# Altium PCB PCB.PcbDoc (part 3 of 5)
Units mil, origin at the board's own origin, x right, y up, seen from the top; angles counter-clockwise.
Board outline 8070.87 x 4448.94 mil, 4 copper layers (Top Layer, Layer 1, Layer 2, Bottom Layer), stack 23.756 mil thick; 263 components, 330 nets, 1677 pads, 1186 vias.
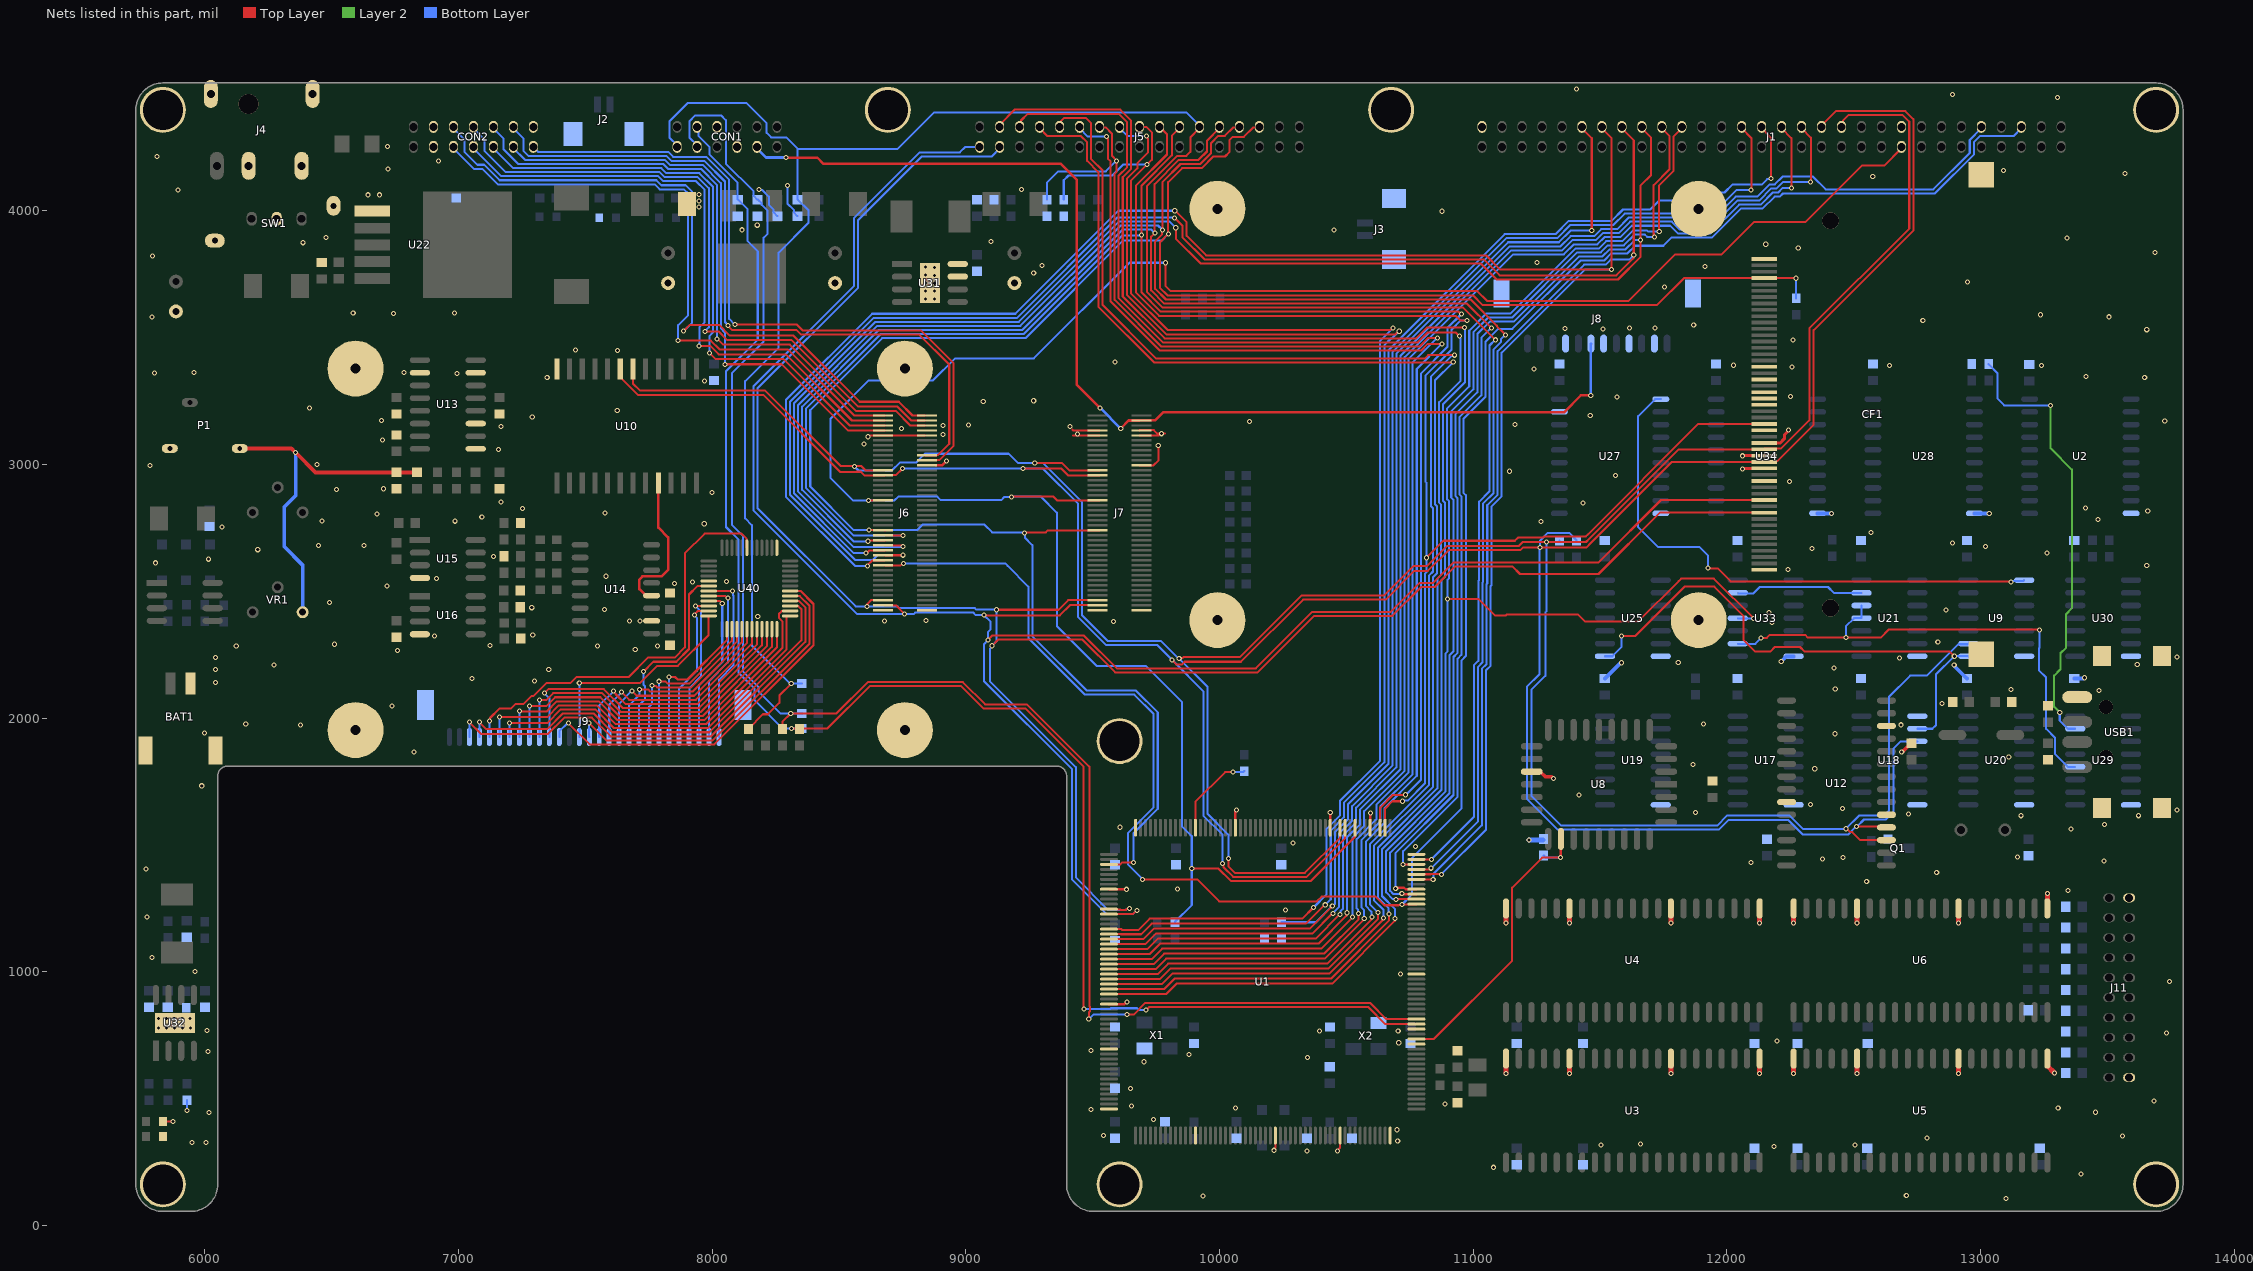
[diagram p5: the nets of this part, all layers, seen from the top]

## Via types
v1: diameter 20, hole 12, Top Layer to Bottom Layer, tented both sides, 1165 vias
v2: diameter 19.68, hole 11.81, Top Layer to Bottom Layer, tented both sides, 10 vias
v3: diameter 27.56, hole 27.56, Top Layer to Bottom Layer, 4 vias
v4: diameter 35.43, hole 35.43, Top Layer to Bottom Layer, 2 vias
v5: diameter 55.12, hole 55.12, Top Layer to Bottom Layer, 2 vias
v6: diameter 66.93, hole 66.93, Top Layer to Bottom Layer, 2 vias
v7: diameter 78.74, hole 78.74, Top Layer to Bottom Layer, 1 vias

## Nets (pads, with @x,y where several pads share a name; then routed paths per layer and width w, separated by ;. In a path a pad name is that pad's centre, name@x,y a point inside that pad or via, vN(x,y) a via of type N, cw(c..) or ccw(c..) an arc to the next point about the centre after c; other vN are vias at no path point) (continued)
D14: CF1.30 J5.3 J6.6 J7.6 U1.12 | length 8550.7
  Top Layer w8: v1(8611,2440) 8613.3,2442.3 8613.3,2451.3 8626.57,2464.57 J6.6@8681.1,2464.57 ; v1(9103.69,2285) 9103.77,2285 9128.33,2309.56 9459.19,2309.56 9588.75,2180 10150.49,2180 10373.49,2403 10681.76,2403 10794.76,2516 10848.01,2516 10930.01,2598 11155,2598 11185,2568 11494.61,2568 11736.25,2809.65 CF1.30@12147.64,2809.65 ; v1(9121.89,2427) 9366,2427 9403.57,2464.57 J7.6@9527.56,2464.57 ; U1.12@9564.65,1246.38 9565.37,1245.65 9609.24,1245.65 9611.89,1243 9630.11,1243 9634.82,1247.7 9642.7,1247.7 v1(9645,1250)
  Bottom Layer w8: v1@8609,2442 v1(8611,2440) ; v1(9103.69,2285) 9103.69,2281.75 9095,2273.07 9095,2145.49 9434,1806.49 9434,1371.63 9562.63,1243 9630.11,1243 9634.82,1247.7 9642.7,1247.7 v1(9645,1250) ; v1@9107,2285.56 9107,2288.93 9121.89,2303.82 v1(9121.89,2427) ; v1@9121.94,2427.06 9121,2428 9040.81,2428 9035.81,2433 8738,2433 8731,2440 v1(8611,2440) ; J5.3@9133.86,4251.97 9133.86,4246.06 9101.8,4214 8826.18,4214 8575.71,3963.54 8575.71,3697.09 8179,3300.37 8179,2826.63 8565.63,2440 v1(8611,2440)
D15: CF1.31 J5.1 J6.4 J7.4 U1.13 | length 8613.1
  Top Layer w8: J6.4@8681.1,2444.88 8682.02,2443.96 8725.11,2443.96 v1(8759,2410.07) ; v1(9072,2406) 9073,2405 9371,2405 9410.88,2444.88 J7.4@9527.56,2444.88 ; v1(9087.4,2307.78) 9105.19,2325.56 9465.82,2325.56 9595.37,2196 10143.86,2196 10366.86,2419 10675.14,2419 10788.14,2532 10841.38,2532 10923.38,2614 11495.35,2614 11741,2859.65 CF1.31@12147.64,2859.65 ; U1.13@9564.65,1226.69 9658.19,1226.69 9672.5,1241 v1(9675,1241)
  Bottom Layer w8: v1(8759,2410.07) 8572.93,2410.07 8163,2820 8163,3307 8559,3703 8559,3970.46 8818.54,4230 8977.04,4230 8999.01,4251.97 J5.1@9055.12,4251.97 ; v1@8761.71,2410.87 8762.51,2410.07 8794.87,2410.07 8800.8,2416 9030.18,2416 9040.18,2406 v1(9072,2406) 9098,2380 9098,2350.12 9088,2340.12 v1@9088,2307.78 ; v1(9087.4,2307.78) 9087.4,2306.4 9072,2291 9072,2145.86 9418,1799.86 9418,1365 9556,1227 9657.89,1227 9671.89,1241 v1(9675,1241)
DACK0#: J5.18 R11.2 U1.16 | length 5511.5
  Top Layer w8: U1.16@9564.65,1167.64 9613.99,1167.64 9617.89,1163.74 9679.74,1163.74 9725,1209 10327,1209 v1(10371,1253) ; J5.18@9685.04,4330.71 9712.29,4330.71 9734.06,4308.94 9734.06,4200.71 9716.36,4183 v1@9715,4183 ; v1(9714,4183) 9714,4182 9651,4119 9651,3675.27 9797.27,3529 10673.02,3529 10681.02,3537 v1(10683.7,3537)
  Bottom Layer w8: R11.2@9386.33,4044 9386.33,4120.33 9405,4139 9578,4139 9622,4183 v1(9714,4183) ; v1(10371,1253) 10423,1305 10423,1563.02 10475,1615.02 10475,1673 10634,1832 10634,3487.3 v1(10683.7,3537)
DACK1#: J1.30 R12.2 U1.18 | length 5453.9
  Top Layer w8: U1.18@9564.65,1128.27 9699.95,1128.27 9741.31,1169.63 10356.25,1169.63 10445,1258.38 v1(10445,1259.28) ; J1.30@12137.8,4330.71 12137.8,4324.8 12174,4288.6 12174,4128 v1(12175,4127)
  Bottom Layer w8: R12.2@10245,1195 10380.71,1195 v1(10445,1259.28) 10448.24,1259.28 10455,1266.04 10455,1549.76 10507,1601.76 10507,1659.75 10666,1818.75 10666,3449 11124.85,3907.85 11324.95,3907.85 11376.95,3959.85 11546.22,3959.85 11591.22,4004.85 11697.96,4004.85 11732.96,4039.85 11842.49,4039.85 11874.65,4072 11991.39,4072 12022.39,4103 12138.14,4103 12159.84,4124.7 12172.7,4124.7 v1(12175,4127)
DACK2#: J1.12 U1.20 | length 4665.6
  Top Layer w8: U1.20@9564.65,1088.9 9716.25,1088.9 9757.62,1130.26 10379.26,1130.26 v1(10475,1226) ; J1.12@11429.13,4330.71 11429.13,4324.8 11468,4285.94 v1(11468,3921.85)
  Bottom Layer w8: v1(10475,1226) 10477.3,1228.3 10477.3,1237.88 10487,1247.58 10487,1536.51 10539,1588.51 10539,1646.49 10698,1805.49 10698,3435.75 11138.1,3875.85 11338.2,3875.85 11384.2,3921.85 v1(11468,3921.85)
DACK3#: J1.34 U1.22 | length 5465.8
  Top Layer w8: U1.22@9564.65,1049.53 9732.56,1049.53 9773.92,1090.89 10400.89,1090.89 v1(10525,1215) ; J1.34@12295.28,4330.71 12295.28,4324.8 12332,4288.08 12332,4115 v1(12329.94,4112.94)
  Bottom Layer w8: v1(10525,1215) 10525,1529.25 10571,1575.25 10571,1633.24 10730,1792.24 10730,3422.49 11151.36,3843.85 11351.46,3843.85 11391.46,3883.85 11483.74,3883.85 11511.74,3911.85 11574.47,3911.85 11619.47,3956.85 11783.9,3956.85 11813.75,3927 11929.25,3927 12042.25,4040 12127.63,4040 12175.63,4088 12196.63,4088 12221.63,4113 12329.89,4113 v1(12329.94,4112.94)
DACK5#: J5.14 R8.2 U1.24 | length 5971.7
  Top Layer w8: J5.14@9527.56,4330.71 9529.86,4328.41 9552.59,4328.41 9576.58,4304.42 9576.58,4216.35 v1@9594,4198.94 ; U1.24@9564.65,1010.16 9748.87,1010.16 9790.23,1051.52 10415.77,1051.52 10571,1206.75 v1(10571,1210) ; v1(9594,4197) 9594,4152.51 9587,4145.51 9587,3648.76 9770.76,3465 10789.25,3465 10823.13,3498.88 v1(10860.12,3498.88)
  Bottom Layer w8: R8.2@9320,4044 9320,4110 9365,4155 9552,4155 v1(9594,4197) ; v1(10571,1210) 10571,1242.75 10561.14,1252.61 10561.14,1520.14 10635,1594 10635,1651.98 10762,1778.98 10762,3402.11 10858.76,3498.88 v1(10860.12,3498.88)
DACK6#: J5.10 U1.26 | length 5919.4
  Top Layer w8: J5.10@9370.08,4330.71 9375.33,4335.96 9375.33,4353.33 9388.33,4366.33 9472.67,4366.33 9494.54,4344.46 9494.54,4203.46 9539,4159 9539,3628.88 9750.88,3417 10809.14,3417 10822.59,3430.46 v1(10927.49,3430.46) ; U1.26@9564.65,970.79 9765.18,970.79 9806.54,1012.15 10429.75,1012.15 10625,1207.39 v1(10625,1234)
  Bottom Layer w8: v1(10625,1234) 10593.14,1265.86 10593.14,1502.53 10827,1736.39 10827,2562.88 10842,2577.88 10842,2827.87 10834,2835.87 10834,3346.11 10916.05,3428.16 10925.2,3428.16 v1(10927.49,3430.46)
DACK7#: J5.6 U1.28 | length 6298.6
  Top Layer w8: J5.6@9212.6,4330.71 9217.85,4335.96 9217.85,4355.85 9244.33,4382.33 9602.61,4382.33 9636.02,4348.92 9636.02,4171.9 9603,4138.88 9603,3655.39 9777.39,3481 10782.63,3481 10822.5,3520.88 10930.76,3520.88 10945.64,3506 v1(10947,3506) ; U1.28@9564.65,931.42 9781.48,931.42 9822.85,972.78 10439.84,972.78 10669.36,1202.3 v1(10669.36,1227.9)
  Bottom Layer w8: v1(10669.36,1227.9) 10667.37,1229.9 10667.37,1249.63 10625.14,1291.86 10625.14,1489.27 10859,1723.14 10859,2549.63 10874,2564.63 10874,2841.12 10866,2849.12 10866,3245.43 10951,3330.43 10951,3495.31 10949.3,3497.02 10949.3,3503.7 v1(10947,3506)
DIREN: R108.1 U29.15 | length 1761.6
  Layer 2 w8: v1(13277,3233) 13277,3063 13361,2979 13361,2433.37 13338,2410.37 13338,2277 13316,2255 13316,2192 13291,2167 13291,2044 v1(13313,2022)
  Bottom Layer w8: R108.1@13033,3396 13033,3394.5 13067,3360.5 13067,3260 13094,3233 v1(13277,3233) ; v1(13313,2022) 13313,1989.82 13345.02,1957.8 U29.15@13374.02,1957.8
DOAB: U10.21 U14.4 | length 585.1
  Top Layer w10: U14.4@7761.34,2483 7738.87,2483 7713,2508.87 7713,2546 7725.21,2558.21 7801.21,2558.21 7827,2584 7827,2712 7788,2751 U10.21@7788,2927
DRQ0: J5.16 U1.17 | length 5215.1
  Top Layer w8: U1.17@9564.65,1147.95 9611.04,1147.95 9611.26,1147.74 9691.58,1147.74 9733.15,1189.31 10340.7,1189.31 10415.28,1263.9 v1(10417.38,1263.9) ; v1(9712,4294) 9712,4290.75 9718,4284.75 9718,4229 9676.5,4187.5 9676.5,4167.13 9635,4125.63 9635,3668.65 9790.65,3513 10693.75,3513 10705.75,3525 v1(10709,3525)
  Bottom Layer w8: J5.16@9606.3,4330.71 9606.3,4324.8 9636.02,4295.09 9710.91,4295.09 v1(9712,4294) ; v1(10417.38,1263.9) 10439,1285.52 10439,1556.39 10491,1608.39 10491,1666.37 10650,1825.37 10650,3469.75 10676.48,3496.23 10680.23,3496.23 v1(10709,3525)
DRQ1: J1.28 U1.19 | length 5211.3
  Top Layer w8: U1.19@9564.65,1108.58 9708.1,1108.58 9749.46,1149.94 10365.99,1149.94 10445.53,1229.49 v1(10447.22,1229.49) ; J1.28@12059.06,4330.71 12059.06,4324.8 12097,4286.86 12097,4083 v1(12095,4081)
  Bottom Layer w8: v1(10447.22,1229.49) 10447.22,1230.39 10461.3,1244.47 ; 10461.3,1244.51 10471,1254.21 10471,1543.14 10523,1595.14 10523,1653.12 10682,1812.12 10682,3442.37 11131.47,3891.85 11331.57,3891.85 11383.57,3943.85 11552.85,3943.85 11597.85,3988.85 11797.15,3988.85 11827,3959 11916,3959 12038,4081 v1(12095,4081)
DRQ2: J1.52 U1.21 | length 6059.5
  Top Layer w8: U1.21@9564.65,1069.21 9724.41,1069.21 9765.77,1110.57 10390.69,1110.57 10500.7,1220.59 10500.7,1230.17 v1(10503,1232.47)
  Bottom Layer w8: v1(10503,1232.47) 10503,1529.88 10555,1581.88 10555,1639.86 10714,1798.86 10714,3429.12 11144.73,3859.85 11344.83,3859.85 11384.83,3899.85 11477.11,3899.85 11505.11,3927.85 11567.85,3927.85 11612.85,3972.85 11790.53,3972.85 11820.37,3943 11922.63,3943 12035.63,4056 12121,4056 12169,4104 12190,4104 12221,4135 12339,4135 12390,4084 12814.37,4084 12958.22,4227.85 12958.22,4279.09 13003.94,4324.8 J1.52@13003.94,4330.71
DRQ3: J1.32 U1.23 | length 5423.8
  Top Layer w8: U1.23@9564.65,1029.84 9740.71,1029.84 9782.08,1071.2 10412.32,1071.2 10548.67,1207.56 10548.67,1229.31 v1(10548.92,1229.56) ; J1.32@12216.54,4330.71 12216.54,4324.8 12255,4286.34 v1(12255,4090)
  Bottom Layer w8: v1(10548.92,1229.56) 10546.62,1231.85 10546.62,1244.5 10541,1250.12 10541,1522.63 10619,1600.63 10619,1658.61 10746,1785.61 10746,3415.86 11157.98,3827.85 11358.08,3827.85 11398.08,3867.85 11490.37,3867.85 11518.37,3895.85 11581.1,3895.85 11626.1,3940.85 11777.27,3940.85 11807.12,3911 11935.88,3911 12048.88,4024 12134.25,4024 12182.25,4072 12203.25,4072 12221.25,4090 v1(12255,4090)
DRQ5: J5.12 U1.25 | length 5706.2
  Top Layer w8: v1(9554.58,4292) 9554.58,4288.75 9560.58,4282.75 9560.58,4204.93 9571,4194.51 9571,3642.14 9764.14,3449 10795.88,3449 10821.88,3475 v1(10877,3475) ; U1.25@9564.65,990.47 9757.02,990.47 9798.38,1031.83 10424.83,1031.83 10598.65,1205.65 10598.65,1212.76 v1(10600.94,1215.06)
  Bottom Layer w8: J5.12@9448.82,4330.71 9448.82,4324.8 9481.62,4292 v1(9554.58,4292) ; v1(10600.94,1215.06) 10599.32,1216.68 10599.32,1237.06 10577.14,1259.24 10577.14,1513.14 10651,1587 10651,1645.24 10778,1772.24 10778,3376 v1(10877,3475)
DRQ6: J5.8 U1.27 | length 5910.1
  Top Layer w8: J5.8@9291.34,4330.71 9291.34,4324.8 9321.27,4294.87 9453.85,4294.87 9478.54,4270.18 9478.54,4196.84 9523,4152.37 9523,3622.25 9744.25,3401 10920,3401 v1(10922,3403) ; U1.27@9564.65,951.1 9773.33,951.1 9814.69,992.46 10432.7,992.46 10641,1200.77 10641,1201.81 10647,1207.81 v1(10647,1211.05)
  Bottom Layer w8: v1(10647,1211.05) 10646.8,1211.26 10646.8,1224.68 10647,1224.89 10647,1244.11 10609.14,1281.98 10609.14,1495.9 10843,1729.76 10843,2556.25 10858,2571.25 10858,2834.5 10850,2842.5 10850,3331 v1(10922,3403)
DRQ7: J5.4 U1.29 | length 6452.3
  Top Layer w8: J5.4@9133.86,4330.71 9133.86,4339.86 9192.33,4398.33 9609.24,4398.33 9652.02,4355.55 9652.02,4165.27 9619,4132.25 9619,3662.02 9784.02,3497 10776,3497 10819.18,3540.18 v1(10966.82,3540.18) ; U1.29@9564.65,911.73 9789.64,911.73 9831,953.09 10444.21,953.09 v1@10691.36,1200.25
  Bottom Layer w8: v1(10692,1209) 10692,1247.63 10641.14,1298.49 10641.14,1482.65 10875,1716.51 10875,2543 10890,2558 10890,2847.75 10882,2855.75 10882,3238 10969,3325 10969,3538 v1(10966.82,3540.18)
GIO1: CON2.5 J6.80 | length 2539.7
  Top Layer w8: v1(7865,3488) 7995,3488 8029.09,3453.91 8298.6,3453.91 8559.6,3192.91 J6.80@8681.1,3192.91
  Bottom Layer w8: CON2.5@6980.32,4251.97 6980.32,4246.06 7061.02,4165.35 7094.51,4165.35 7155.58,4104.28 7773.67,4104.28 7793.35,4084.6 7888.84,4084.6 7905.26,4068.18 7905.26,3588.26 7866,3549 7866,3489 v1(7865,3488)
GIO2: CON2.6 J6.79 | length 2750.2
  Top Layer w8: v1(7888,3526) 7912,3550 8028,3550 8070,3508 8321.01,3508 8582.01,3247 8736,3247 8790.09,3192.91 J6.79@8838.58,3192.91
  Bottom Layer w8: CON2.6@6980.32,4330.71 6980.32,4324.8 7023.62,4281.5 7023.62,4232.28 7074.55,4181.35 7101.14,4181.35 7162.21,4120.28 7780.3,4120.28 7799.98,4100.6 7895.46,4100.6 7921.26,4074.8 7921.26,3684 7921.26,3559.26 v1(7888,3526)
GIO3: CON2.7 J6.78 | length 2465.7
  Top Layer w8: v1(7948,3466) 7994,3466 8025.77,3434.23 8290.45,3434.23 8551.45,3173.23 J6.78@8681.1,3173.23
  Bottom Layer w8: CON2.7@7059.06,4251.97 7059.06,4246.06 7168.83,4136.28 7786.92,4136.28 7806.61,4116.6 7936.57,4116.6 7970.93,4082.24 7970.93,3560.93 7950,3540 7950,3468 v1(7948,3466)
GIO4: CON2.8 J6.77 | length 2641
  Top Layer w8: v1(7972,3524) 8026,3524 8060,3490 8313.55,3490 8574.55,3229 8728.91,3229 8784.68,3173.23 J6.77@8838.58,3173.23
  Bottom Layer w8: CON2.8@7059.06,4330.71 7059.06,4324.8 7102.36,4281.5 7102.36,4236.22 7186.3,4152.28 7793.55,4152.28 7813.24,4132.6 7943.2,4132.6 7986.93,4088.87 7986.93,3540.18 7972,3525.25 v1(7972,3524)
GIO5: CON2.9 J6.76 | length 2405.5
  Top Layer w8: v1(7988.94,3439.94) 7989.06,3439.94 8013,3416 8280.84,3416 8543.3,3153.54 J6.76@8681.1,3153.54
  Bottom Layer w8: CON2.9@7137.8,4251.97 7137.8,4246.06 7215.58,4168.28 7800.18,4168.28 7819.86,4148.6 7949.83,4148.6 8002.93,4095.5 8002.93,3519.93 7990,3507 7990,3441 v1(7988.94,3439.94)
GIO6: CON2.10 J6.75 | length 2572
  Top Layer w8: v1(8019.92,3494.2) 8021.8,3494.2 8044,3472 8306.09,3472 8567.09,3211 8724.28,3211 8781.73,3153.54 J6.75@8838.58,3153.54
  Bottom Layer w8: CON2.10@7137.8,4330.71 7137.8,4324.8 7177.17,4285.43 7177.17,4243.41 7236.29,4184.28 7806.81,4184.28 7826.49,4164.6 7956.45,4164.6 8018.93,4102.12 8018.93,3495.18 v1(8019.92,3494.2)
GIO7: CON2.11 J6.74 | length 2340.8
  Top Layer w8: v1@8051,3394.86 8274.14,3394.86 8535.14,3133.86 J6.74@8681.1,3133.86
  Bottom Layer w8: CON2.11@7216.54,4251.97 7216.54,4246.06 7262.32,4200.28 7813.43,4200.28 7833.12,4180.6 7963.08,4180.6 8034.93,4108.75 8034.93,3536.07 8051,3520 v1(8051,3394)
GIO8: CON2.12 J6.63 | length 2893.4
  Top Layer w8: v1(8062.06,3547.06) 8062.06,3546.94 8079.82,3529.18 8333.02,3529.18 8350.9,3511.31 8817.45,3511.31 8935,3393.76 8935,3081 8890.35,3036.35 8885.82,3036.35 8885.62,3036.16 8839.31,3036.16 J6.63@8838.58,3035.43
  Bottom Layer w8: CON2.12@7216.54,4330.71 7216.54,4324.8 7255.91,4285.43 7255.91,4236.22 7275.84,4216.28 7820.06,4216.28 7839.75,4196.6 7969.71,4196.6 8050.93,4115.38 8050.93,3561.32 8062.06,3550.19 v1(8062.06,3547.06)
GIO9: CON2.13 J6.61 | length 2793.2
  Top Layer w8: v1(8090,3551.18) 8334.65,3551.18 8358.52,3527.31 8824.08,3527.31 8951,3400.39 8951,3072 8895.47,3016.47 J6.61@8839.31,3016.47
  Bottom Layer w8: CON2.13@7295.28,4251.97 7295.28,4250.69 7313.68,4232.28 7826.69,4232.28 7846.37,4212.6 7976.34,4212.6 8066.93,4122.01 8066.93,3574.25 v1(8090,3551.18)
GND: BAT1.0 BAT1.1 C1.1 C2.1 C3.2 C4.1 C5.2 C6.2 C7.2 C8.2 C9.1 C10.2 C11.2 C12.2 C13.2 C14.2 C15.2 C16.2 C17.2 C18.2 C19.2 C21.2 C22.2 C23.2 C24.2 C25.2 C26.2 C27.2 C28.2 C29.2 C30.2 C31.2 C43.1 C44.2 C45.1 C48.1 C52.1 C53.1 C54.1 C56.2 C58.1 C59.1 C60.1 C61.1 C62.2 C63.1 C64.1 C65.2 C66.2 C68.2 C72.2 C73.2 C74.2 C75.2 C76.2 C77.2 C78.2 C80.2 C83.2 C84.2 C85.2 C86.2 C87.2 C88.2 C89.2 C90.2 C91.2 C92.2 C93.2 C94.2 C95.2 C96.2 C97.2 C98.2 C99.2 C100.2 C101.2 C102.2 C103.2 C104.1 C105.1 C106.2 C108.2 C109.2 C110.2 C111.2 C112.2 C113.2 C114.2 C115.2 C116.2 C121.2 CF1.0 CF1.1 CF1.8 CF1.9 CF1.10 CF1.11 CF1.12 CF1.14 CF1.15 CF1.16 CF1.17 CF1.39 CF1.50 CON1.6 CON1.7 CON2.3 CON2.4 CON2.14 D3.A DM1.1 DM2.1 DM3.1 DM4.1 DM5.1 DM6.1 DM7.1 DM8.1 J1.2 J1.44 J2.0 J3.0 J4.2 J4.3 J6.1 J6.2 J6.59 J6.71 J6.72 J6.73 J7.1 J7.2 J7.59 J7.71 J7.72 J7.73 J7.74 J8.0 J8.4 J8.7 J8.9 J8.11 J9.0 J11.2 J11.20 LED2.2 LED5.2 LED6.2 P1.1 Q1.E R8.1 R9.1 R10.1 R11.1 R12.1 R25.2 R101.2 R109.1 R132.1 R134.2 SW1.0 SW1.2 T1.1 T2.1 T3.1 T4.1 T5.1 T6.1 T7.1 T8.1 U1.8 U1.31 U1.40 U1.52 U1.65 U1.81 U1.94 U1.104 U1.118 U1.121 U1.132 U1.156 U1.161 U1.169 U1.188 U1.208 U2.10 U3.22 U3.29 U3.37 U3.42 U4.22 U4.29 U4.37 U4.42 U5.22 U5.29 U5.37 U5.42 U6.22 U6.29 U6.37 U6.42 U8.16 U9.7 U10.12 U12.5 U12.12 U12.23 U13.2 U13.9 U13.11 U13.15 U14.2 U15.4 U16.4 U17.8 U18.1 U18.8 U19.8 U20.8 U21.7 U22.1 U25.7 U27.10 U27.19 U28.10 U29.8 U30.7 U31.0 U31.7 U31.8 U32.0 U33.7 U34.10 U40.17 USB1.0 USB1.GND X1.2 X2.2 | length 3467.3
  Top Layer w8: LED5.2@5834.65,409.45 v1(5874.02,409.45) ; v1(8614,3109) 8617.25,3109 8621.86,3113.61 8680.54,3113.61 8681.1,3114.17 J6.71@8838.58,3114.17 ; 9420,3137 9423.14,3133.86 J7.74@9527.56,3133.86 ; 9423.14,3114.17 J7.72@9527.56,3114.17 ; U1.8@9564.65,1325.12 9564.7,1325.06 9632.94,1325.06 v1(9633,1325) ; J7.59@9685.04,2996.06 9740.06,2996.06 9759,3015 v1(9759,3075) ; J7.71@9685.04,3114.17 9760.93,3114.17 v1@9767.75,3121 ; J7.73@9685.04,3133.86 9685.96,3134.78 9741.22,3134.78 9755,3121 v1@9767.75,3121 ; 9784.51,3121 v1(9771,3121) v1@9767.75,3121 ; v1(10215,296) 10215,299.25 10220.47,304.72 U1.81@10220.47,354.33 ; v1(10465,294) 10465,295.52 10476.38,306.9 U1.94@10476.38,354.33
  Top Layer w10: J6.59@8880.83,2996.06 8905.95,2996.06 8923.83,3013.94 v1(8924.06,3013.94) ; U1.31@9564.65,872.36 9625.2,872.36 9632.84,880 v1(9635,880) ; U1.188@10062.99,1567.56 10062.99,1630.29 10067,1634.29 v1(10067,1637) ; U1.169@10437.01,1567.56 v1(10437,1627) ; U1.161@10594.49,1567.56 10594.74,1567.81 10594.74,1625.74 v1(10595,1626)
  Top Layer w12: v1(12063,2982) 12065.16,2982 12067.81,2984.65 CF1.9@12147.64,2984.65 ; v1(12063,3034) 12063.32,3034.32 12147.32,3034.32 CF1.10@12147.64,3034.65 ; CF1.11@12147.64,3084.65 12211.19,3084.65 12227.27,3100.73 12227.27,3116.11 12244,3132.84 v1(12244,3135)
  Top Layer w15: U8.16@11231.46,1788.62 11264.97,1788.62 11285.09,1768.5 11310.15,1768.5 11316.65,1762 v1(11318,1762) ; v1(12690,1866) 12690.96,1866.96 12693.44,1866.96 12727.5,1901.02 C62.2@12729,1901.02
  Top Layer w20: v1(11130,599.45) U3.42@11130,657.45 ; v1(11130,1191.45) U4.42@11130,1249.45 ; v1(11380,599.45) U3.37@11380,657.45 ; v1(11380,1191.45) U4.37@11380,1249.45 ; v1(11780,599) U3.29@11780,657.45 ; v1(11780,1191.45) U4.29@11780,1249.45 ; v1(12130,599) U3.22@12130,657.45 ; v1(12130,1191.45) U4.22@12130,1249.45 ; v1(12264,599) U5.42@12264,657.45 ; v1(12264,1191.45) U6.42@12264,1249.45 ; v1(12514,599) U5.37@12514,657.45 ; v1(12514,1191.45) U6.37@12514,1249.45 ; v1(12914,599.45) U5.29@12914,657.45 ; v1(12914,1191.45) U6.29@12914,1249.45 ; U5.22@13264,657.45 13264,629 v1(13292,601) ; U6.22@13264,1249.45 13264.77,1250.21 13264.77,1307.77 v1(13265,1308)
  Bottom Layer w8: v1(5929.13,452.76) R132.1@5929.13,493.8 ; v1(8185,4084) 8187.3,4081.7 8197.25,4081.7 8223.49,4055.47 8223.49,4023.52 8242.5,4004.51 8242.5,3993.5 8257,3979 C8.2@8258.5,3979 ; v1(8297,4099) 8297,4028.51 8322.02,4003.49 8322.02,3993.5 8336.52,3979 C7.2@8337,3979 ; R9.1@11275,1520 R9.1@11278,1523
  Bottom Layer w15: C92.2@11519,2155.98 11520.5,2155.98 11581.56,2217.04 11585.04,2217.04 v1(11586,2218) ; v1(12215,2223) 12215.13,2223 12234.65,2242.52 U33.7@12263.78,2242.52 ; U34.10@12358.27,2807.09 12358.32,2807.05 v1(12413,2807) v1(12413,2807) ; v1(12897,2209) 12897.96,2208.04 12897.96,2204.52 12946.5,2155.98 C85.2@12948,2155.98 ; U28.10@12976.38,2807.09 12976.43,2807.05 v1(13035,2807) v1(13035,2807) ; C88.2@13370,2155.98 13405.63,2155.98 13408.65,2159 v1(13410,2159)
  Bottom Layer w20: v1(11221,1520) R9.1@11275,1520
  other v1: 13101,106 9935,115 12708,117 13396,202 11081,229 10346,293 12187,311 11504,317 12505,317 11660,320 10703,332 12789,344 13560,353 9543,355 10700,377 9741,418 13454,446 9494,457 10063,463 13307,463 9654,470 10890,479 13685,490 9649,540 9702,645 10348,661 9880,674 9494,689 10707,720 12199,727 13734,758 10394,766 10705,767 5818,778.36 5849.25,778.36 5880.5,778.36 5911.75,778.36 5943,778.36 5817,816.36 5848.25,816.36 5879.5,816.36 5910.75,816.36 5942,816.36 13745,961 10714,991 10260,1243 13345,1320 9834,1326 12552,1355 12828,1391 12096,1431 13487,1437 12378,1445 12459,1451 13147,1452 10773.56,1493.44 10291,1507 13357,1562 9607.44,1569.56 13489,1580 13160,1615 13623,1615 12716,1621 11877,1627 13776,1638 12456,1644 12331,1660 11418,1696 5988,1733 12347.14,1800.18 11867,1817 13112.04,1847.02 6824,1867 12427.14,1938.18 5998,1941 6377.95,1972.44 12687.08,1973.53 6161.42,1976.38 11908,1977 6738,2047 12849,2057 13467,2109 13120,2113 12428,2114 6042,2140 7299,2146 7054,2156 6042,2191 7356,2191 12423.14,2197.18 6273,2209 13618.56,2211.56 11809,2219 12681,2236 6042,2239 13776,2241 6760,2267 7697,2271 6124,2284 7549,2284 7784,2284 7125.14,2286.18 6512,2291 12832.14,2299.18 6905,2323 7293,2327 12178,2377 9582,2381 7675,2382 7715,2382 8680,2383 8844,2384 8180,2401 12166,2416 12865.14,2425.18 7575,2428 7289,2435 6492,2456 6718,2520 7851,2530 7923,2537 8057,2538 6914,2551 7582,2559 12241,2586 13656,2602 5806.14,2612.18 6015.14,2626.18 7139,2637 13263,2651 6208.73,2663.65 12336,2669 13020,2676 6448,2680 6628,2680 12890,2691 12569,2731 6067.14,2753.18 7969,2766 11268,2775 6987,2776 6462,2777 13463,2783 7092,2792 6679,2805 7577,2808 13660,2816 7252,2826 13415,2828 11434,2848 7167,2851 8000,2890 6519,2901 6704,2904 12247,2933 11561,2956 11144,2973 5784,2996 6442.29,2999.29 7158,3059 8599,3081 6700,3096 8911,3118 9441,3120 8746.14,3142.18 9411,3149 7168,3150 8911,3153 9011,3156 11166,3157 10119,3170 13727,3171 6696,3173 7291,3187 11462,3193 7626,3212 6413,3222 9069,3248 9268,3251 11567,3265 12252,3268 7970,3329 13648,3342 7350,3343 13417,3346 6994,3359 5802,3360 6785,3363 11241,3376 12257,3384 12642,3390 13241,3390 12026,3391 9589,3403 7627,3449 7461,3451 12261,3491 13656,3531 11512,3534 11363,3536 11617,3537 11717,3537 11870,3549 12773,3567 5792,3581 13508,3582 13237,3590 6744.14,3594.18 6585.14,3596.18 6985.14,3596.18 8876,3652 8842,3652.75 8876,3683 8842,3684 11754,3700 8876,3714.25 8842,3715.25 12950,3719 8842,3746.5 8876,3745.5 9268,3754 8876,3776.75 8842,3777.75 11914,3781 9301,3785 11252.64,3795.35 5794,3821 13689,3836 12282,3854 12154,3868 6388,3874 9099,3878 13341,3893 6477,3894 10452,3924 8118,3925 8178,3943 10877,3998 7948.93,4014.23 7948.93,4039.11 6643,4063 6689,4063 7948.93,4064 5894,4081 9219,4084 12575.79,4134.82 13571,4147 13092,4158 6723,4164 6922,4196 5811,4214 6721,4253 13304,4446 12891,4458 11408.14,4479.18
  other v2: 5948.82,326.77 6003.94,326.77 6015.75,444.88 6011.81,685.04 6007.87,767.72 5961.97,999.98 5791.34,1055.12 5772.99,1216.52 5769.05,1405.49 5958.03,3362.19
  other v5: 13496.06,1846.46 13496.06,2043.31
  other v6: 12409.45,2433.07 12409.45,3960.63
  other v7: 6173.23,4421.26
HSYNC1: CON1.9 J7.77 J8.6 | length 4487.9
  Top Layer w10: CON1.9@8177.17,4246.06 CON1.9@8177.17,4251.97 ; v1@8292,4209 8415,4209 8438,4186 9374,4186 9437,4123 9437,3315 v1(9530,3222) ; v1(9611,3142) 9611,3142.18 9641.97,3173.15 9684.96,3173.15 9685.04,3173.23 9746.23,3173.23 9778.5,3205.5 11358.24,3205.5 11425.49,3272.75 v1@11464,3272.75
  Bottom Layer w10: CON1.9@8177.17,4251.97 8177.17,4246.06 8213.23,4210 v1(8292,4210) ; v1(9530,3222) 9530.5,3222 9610.5,3142 v1(9611,3142) ; v1(11464,3272) 11464.48,3272.48 11464.48,3475.9 J8.6@11464.96,3476.38
IO378#: U9.8 U18.2 U25.8 | length 2136.5
  Top Layer w8: v1(11586,2323) 11638.63,2323 11833.63,2518 11951,2518 12066,2403 12066,2308.37 12112.37,2262 12171.75,2262 12189.75,2280 12289.01,2280 12306.01,2263 12878,2263 v1(12897.24,2243.76)
  Bottom Layer w8: U25.8@11520.16,2243.7 11549.16,2243.7 11586,2280.54 v1(11586,2323) ; U18.2@12751.5,1957.8 12810.8,1957.8 12825,1972 12825,2172 12896.76,2243.76 v1(12897.24,2243.76) ; v1@12897.15,2243.85 12952.61,2243.85 U9.8@12952.76,2243.7
IO378R: U9.1 U27.1 | length 2197.3
  Top Layer w8: v1(11927,2591) 11929,2589 11966,2589 12016,2539 13119,2539 v1(13121,2537)
  Bottom Layer w8: U27.1@11740.16,3257.09 11717.69,3257.09 11651,3190.4 11651,2752.37 11728.37,2675 11892,2675 11927,2640 v1(11927,2591) ; v1(13121,2537) 13124.25,2537 13128.27,2541.02 13170.08,2541.02 U9.1@13172.76,2543.7
IOCHCK: R51.1 U1.196 | length 345.1
  Top Layer w8: U1.196@9905.51,1567.56 9905.51,1670.14 10022.54,1787.17 v1(10054,1787.17)
  Bottom Layer w8: v1(10054,1787.17) 10094.17,1787.17 R51.1@10098,1791
IOCS16#: CF1.24 J5.30 J6.34 J7.34 R56.1 U1.3 | length 8640.4
  Top Layer w8: v1(8619.19,2741) 8619.61,2740.58 8680.68,2740.58 J6.34@8681.1,2740.16 ; v1(9231,2730) 9233,2732 9316,2732 9324.16,2740.16 J7.34@9527.56,2740.16 ; U1.3@9564.65,1423.54 9609.49,1423.54 9616.94,1431 v1(9662,1431) ; J5.30@10157.48,4330.71 10154.22,4327.45 10132.45,4327.45 10096,4291 10052,4291 10039,4278 10039,4231 10022,4214 9976.48,4214 9930.82,4168.35 9853.35,4168.35 9798,4113 9798,3910 v1(9799,3909) 9765,3875 9765,3697.04 9796.04,3666 11000,3666 11037,3629 11726,3629 11831.65,3734.65 CF1.24@12148.64,3734.65 12148.96,3734.32 12272.68,3734.32 v1(12273,3734)
  Bottom Layer w8: v1@8619.19,2740.93 8807.93,2740.93 8830,2763 9073,2763 9104,2732 9229,2732 v1(9231,2730) ; v1(8619.19,2741) 8558.78,2741 8387,2912.78 8387,3214.22 8670.78,3498 9235.49,3498 9619.49,3882 9772,3882 v1(9799,3909) ; v1@9231.66,2730.66 9233.3,2729.02 9233.3,2711.7 9263,2682 9263,2322.25 9476.75,2108.51 9671.03,2108.51 9757,2022.54 9757,1642 9662,1547 v1(9662,1431) ; v1(12273,3734) 12273,3656 R56.1@12274,3655
IOR#: CF1.34 J1.36 J6.56 J7.56 R61.1 U1.166 U10.7 U12.4 U18.3 | length 12727.4
  Top Layer w8: U10.7@7638,3375.82 7644,3369.82 7644,3337 7707,3274 8202,3274 8505.85,2970.15 8568.11,2970.15 8568.96,2971 8586,2971 8600.31,2956.69 8681.1,2956.69 8682.02,2957.61 8724.61,2957.61 v1(8751,2984) ; v1(9226,2983.86) 9375.83,2983.86 9403,2956.69 J7.56@9527.56,2956.69 ; v1(9813.79,2228.79) 9813.79,2227.98 9829.77,2212 9852.72,2212 9862.72,2222 10084.77,2222 10329.77,2467 10655.25,2467 10768.25,2580 10821.5,2580 10903.5,2662 11186.63,2662 11196.63,2672 v1(11264,2672) 11445.87,2672 11464.88,2691.01 11465.01,2691.01 11783.65,3009.65 CF1.34@12147.64,3009.65 12150.89,3012.9 12200.11,3012.9 12343,3155.79 12343,3528.96 12735.72,3921.68 12735.72,4361.28 12704,4393 12430.4,4393 12374.02,4336.61 J1.36@12374.02,4330.71 ; v1(10013,1426) 10015.3,1423.7 10015.3,1412.96 10054.26,1374 10343.63,1374 10495.33,1525.71 10495.33,1566.83 U1.166@10496.06,1567.56 ; v1(12511,1573) 12591.83,1573 12592.68,1572.15 12626.67,1572.15 U12.4@12629.92,1568.9
  Bottom Layer w8: v1@8751,2983.8 9225.93,2983.8 v1(9226,2983.86) 9303.63,2983.86 9443,2844.49 9443,2397.79 9552.14,2288.65 9753.93,2288.65 v1(9813.79,2228.79) ; v1@9812,2227 9814.17,2224.83 9817.67,2224.83 9937,2105.49 9937,1615.67 10013,1539.67 v1(10013,1426) ; R61.1@11408,2699 11408,2700.5 11378.5,2730 11294.89,2730 11264,2699.11 v1(11264,2672) 11262,2670 11262,2173 11212,2123 11212,1682 11334,1560 11968.63,1560 12007.63,1599 12241.63,1599 12299.63,1541 12479,1541 v1(12511,1573) 12514.25,1573 12541.25,1600 12627.63,1600 12657,1629.37 12657,1879 12685.8,1907.8 U18.3@12751.5,1907.8
IORDY: J1.43 J6.46 J7.46 R52.1 U1.164 | length 9220.7
  Top Layer w8: v1(8617,2858.27) J6.46@8681.1,2858.27 ; v1(9180,2871.47) 9181.93,2873.4 9344.6,2873.4 9359.73,2858.27 J7.46@9527.56,2858.27 ; v1(9787,3795) 9787,3704 9808,3683 11017,3683 11055,3645 11613.25,3645 11795.25,3827 11979.25,3827 12107.25,3955 12310.11,3955 12533.11,4178 12620.91,4178 12688.98,4246.06 J1.43@12688.98,4251.97 ; v1(9891,1407) 9996.11,1407 10045.11,1358 10361.04,1358 10534.7,1531.67 10534.7,1566.83 U1.164@10535.43,1567.56
  Bottom Layer w8: v1(9180,2871.47) 9152.39,2871.47 9139.93,2859 8901.86,2859 8887.66,2873.2 8734.2,2873.2 8719.27,2858.27 v1(8617,2858.27) 8554.65,2858.27 8467,2945.92 8467,3181.08 8616.92,3331 8871,3331 8958,3418 9268.63,3418 9645.63,3795 v1(9787,3795) ; v1@9180,2872 9181.33,2873.33 9295.36,2873.33 9359,2809.7 9359,2363 9517.49,2204.51 9710.8,2204.51 9853,2062.3 9853,1572 9891,1534 v1(9891,1407) 9891,1262.5 9825,1196.5 R52.1@9825,1195
IOW#: CF1.35 J1.38 J6.58 J7.58 R60.1 U1.167 U9.9 U10.6 U12.3 | length 12969.3
  Top Layer w8: U10.6@7688,3375.82 7688,3319 7716.03,3290.97 8209.03,3290.97 8506.42,2993.58 v1@8559.58,2993.58 ; v1(8561,2992.15) v1@8559.58,2993.58 ; J6.58@8681.1,2976.38 8680.72,2976 8606.38,2976 8588.8,2993.58 v1@8559.58,2993.58 ; v1(9272,3005.86) 9379.14,3005.86 9408.62,2976.38 J7.58@9527.56,2976.38 ; v1(9841.61,2234) 9843.9,2236.3 9854.39,2236.3 9858.09,2240 10080.15,2240 10323.15,2483 10648.63,2483 10765.63,2600 10818.87,2600 10897.87,2679 11181,2679 11196,2694 v1(11290,2694) 11445.25,2694 11458.25,2707.01 11458.38,2707.01 11811.02,3059.65 CF1.35@12147.64,3059.65 12150.89,3062.9 12214.9,3062.9 12326,3174 12326,3536 12719.72,3929.72 12719.72,4351.28 12694,4377 12480,4377 12458,4355 12458,4335.96 J1.38@12452.76,4330.71 ; v1(10035.28,1447) 10035.28,1415.61 10060.89,1390 10337,1390 10475.65,1528.65 10475.65,1566.83 U1.167@10476.38,1567.56 ; v1(12470.44,1563.56) 12473.69,1563.56 12486.63,1550.62 12495.38,1550.62 12527.1,1518.9 U12.3@12629.92,1518.9
  Bottom Layer w8: v1(8561,2992.15) 8577.15,2976 8709,2976 8740,3007 8804,3007 8839,3042 9169,3042 9205.14,3005.86 v1(9272,3005.86) ; v1@9272.07,3005.93 9272.14,3005.86 9304.25,3005.86 9459,2851.12 9459,2404.42 9558.77,2304.65 9769.04,2304.65 9839.7,2234 v1(9841.61,2234) ; v1@9843,2230 9846,2230 9953,2123 9953,1622.3 10035.28,1540.01 v1(10035.28,1447) ; R60.1@11341,2699 11336,2694 v1(11290,2694) 11290,2421.88 11285,2416.88 11285,2166 11230,2111 11230,1694 11348,1576 11962,1576 12001,1615 12248.25,1615 12300.25,1563 12469.89,1563 12522.89,1616 12621,1616 12640,1635 12640,2084 12723,2167 12789.37,2167 12913.39,2291.02 12950.08,2291.02 U9.9@12952.76,2293.7
IRQ1: U40.1
IRQ3: J1.14 J6.22 U1.152 | length 7988.5
  Top Layer w8: v1(8612.39,2599.39) 8612.39,2602.59 8631.12,2621.32 J6.22@8680.38,2621.32 ; v1(9824,4000) 9826.11,4000 9871,3955.11 9871,3900.74 9947.74,3824 11051,3824 11107,3768 v1(11546,3768) 11546,4286.68 11507.87,4324.8 J1.14@11507.87,4330.71 ; U1.152@10776.77,1384.17 10832.06,1384.17 10833.89,1386 10873,1386 v1(10875,1384)
  Bottom Layer w8: v1(8612.39,2599.39) 8564.62,2599.39 8291,2873.02 8291,3253.98 8631.02,3594 9195.73,3594 9601.73,4000 v1(9824,4000) ; v1(10875,1384) 11051,1560 11051,2187.76 11069,2205.76 11069,2520.42 11072,2523.42 11072,2833.01 11113,2874.01 11113,3440.29 11440.71,3768 v1(11546,3768)
IRQ4: J1.16 J6.24 U1.151 | length 8262
  Top Layer w8: J6.24@8681.1,2641.73 8681.24,2641.87 8752.87,2641.87 v1(8753,2642) ; v1(9823,3972) 9855,3940 9855,3894.11 9941.11,3808 11042,3808 11105,3745 11564.92,3745 11631.9,3811.99 11631.9,3823.79 v1(11633.56,3825.44) 11633.56,4277.86 11586.61,4324.8 J1.16@11586.61,4330.71 ; U1.151@10776.77,1364.49 10777.02,1364.24 10842.76,1364.24 v1(10843,1364)
  Bottom Layer w8: v1(8753,2642) 8652,2642 8633,2623 8563.65,2623 8307,2879.65 8307,3247.35 8637.65,3578 9202.35,3578 9598.35,3974 9821,3974 v1(9823,3972) ; v1(10843,1364) 10844.11,1365.11 10844.11,1386 11035,1576.89 11035,2194.39 11053,2212.39 11053,2527.05 11056,2530.05 11056,2839.63 11097,2880.63 11097,3446.92 11437.92,3787.85 11523.5,3787.85 11542.66,3807 11615.11,3807 v1(11633.56,3825.44)
IRQ5: J1.18 J6.26 U1.149 | length 8360.9
  Top Layer w8: v1(8606,2650) 8609.25,2650 8620.66,2661.42 J6.26@8681.1,2661.42 ; v1(9828,3933) 9828,3890 9926,3792 11030,3792 11093,3729 11571.54,3729 11661,3818.46 v1(11661,3884) 11661,4100 11702,4141 11702,4288.16 11665.35,4324.8 J1.18@11665.35,4330.71 ; v1(10695.14,1328.23) 10698.38,1328.23 10701.16,1331 10728.11,1331 10733.99,1325.12 U1.149@10776.77,1325.12
  Bottom Layer w8: v1(8606,2650) 8559.27,2650 8323,2886.27 8323,3240.73 8644.27,3562 9208.98,3562 9604.98,3958 9803,3958 v1(9828,3933) ; v1(10695.14,1328.23) 10694,1329.36 10694,1467.63 10923,1696.63 10923,2240.78 10938,2255.78 10938,2867.63 10930,2875.63 10930,3197.45 11017,3284.45 11017,3514 11066.13,3563.13 11161.25,3563.13 11417.96,3819.85 11510.25,3819.85 11538.25,3847.85 11600.98,3847.85 11637.14,3884 v1(11661,3884)
IRQ6: J1.20 U1.148 | length 3806.5
  Top Layer w8: v1(10719,1309) 10722.25,1309 10725.81,1305.43 U1.148@10776.77,1305.43 U1.148@10777.5,1306.16 ; v1(11714.64,3896.85) 11712.34,3899.14 11712.34,3909.39 11712,3909.73 11712,4101 11773.81,4162.81 11773.81,4295.09 11744.09,4324.8 J1.20@11744.09,4330.71
  Bottom Layer w8: v1(10719,1309) 10716.7,1306.7 10704.73,1306.7 10704.25,1306.23 10686.02,1306.23 10673.14,1319.12 10673.14,1469.39 10907,1703.25 10907,2247.41 10922,2262.41 10922,2861.01 10914,2869.01 10914,3209.26 11001,3296.26 11001,3520.63 11059.5,3579.13 11074.5,3579.13 11154.62,3579.13 11411.34,3835.85 11503.62,3835.85 11531.62,3863.85 11594.36,3863.85 11636.51,3906 11677.06,3906 11686.22,3896.85 v1(11714.64,3896.85)
IRQ7: J1.22 U1.147 U33.11 | length 5289.6
  Top Layer w8: v1@10703.25,1287 10729.11,1287 10730.36,1285.75 U1.147@10776.77,1285.75 ; v1(10900,2469) 11022,2469 11086.87,2404.13 11128.13,2404.13 11133,2409 11413,2409 11441,2381 11651.37,2381 11810.44,2540.06 11820.37,2550 11949,2550 v1(12106,2393) ; v1(11734,3918.85) 11734,4100.37 11789.81,4156.18 11789.81,4291.78 11822.83,4324.8 J1.22@11822.83,4330.71
  Bottom Layer w8: v1(10697,1284) 10694.7,1286.3 10683.33,1286.3 10657.14,1312.49 10657.14,1476.02 10891,1709.88 10891,2254.04 10900,2263.04 10900,2545.37 10906,2551.37 10906,2854.38 10898,2862.38 10898,3221.07 10985,3308.07 10985,3527.25 11052.87,3595.13 11147.99,3595.13 11404.71,3851.85 11496.99,3851.85 11524.99,3879.85 11587.73,3879.85 11629.88,3922 11686.43,3922 11689.58,3918.85 v1(11734,3918.85) ; U33.11@12043.78,2392.52 12044.61,2393.35 12105.65,2393.35 v1(12106,2393)
IRQ9: J1.56 J6.20 U1.146 | length 8144.8
  Top Layer w8: J6.20@8681.1,2602.36 8743.12,2602.36 8750.75,2610 v1(8754,2610) ; v1(9697,1363) 9698,1364 9912,1364 9999,1277 10384.04,1277 10403.04,1296 10616,1296 10650,1262 10706.11,1262 10706.82,1262.7 10717.7,1262.7 v1(10720,1265) 10720.53,1265.53 10776.24,1265.53 U1.146@10776.77,1266.06
  Bottom Layer w8: v1(8754,2610) 9155.07,2610 9165,2600.07 9165,2599.89 9247,2517.89 9247,2315.63 9470.12,2092.51 9664.41,2092.51 9741,2015.91 9741,1648.63 9640,1547.63 9640,1421.89 9697,1364.89 v1(9697,1363) ; v1(10720,1265) 10759,1304 10759,1448 10782.44,1471.44 10782.67,1471.44 10955,1643.77 10955,2227.53 10972,2244.53 10972,2878.89 10962,2888.89 10962,3179 11049,3266 11049,3483.77 11099.35,3534.13 11154.87,3534.13 11424.59,3803.85 11516.88,3803.85 11544.88,3831.85 11608.85,3831.85 11639,3862 11750,3862 11783,3895 11942.51,3895 12055.51,4008 12140.88,4008 12188.88,4056 12209.88,4056 12221.88,4068 12821,4068 12974.22,4221.22 12974.22,4270.18 12998.04,4294 13130.61,4294 13161.42,4324.8 J1.56@13161.42,4330.71
IRQ10: J5.28 J6.28 U1.153 | length 7247.8
  Top Layer w8: J6.28@8681.1,2681.1 8744.65,2681.1 8749.75,2676 v1(8753,2676) ; v1(9775.61,3924.39) 9773.31,3922.09 9773.31,3905.94 9747,3879.63 9747,3692.41 9789.41,3650 10991.23,3650 11094.11,3547.11 11094.11,3544.89 v1(11128,3511) ; v1@9776,3924.39 9776,4113.63 9846.72,4184.35 9924.2,4184.35 9967,4227.15 9967,4266.9 9995.19,4295.09 10021.09,4295.09 10053.71,4327.71 10075.74,4327.71 J5.28@10078.74,4330.71 ; U1.153@10776.77,1403.86 10827.61,1403.86 10831.75,1408 v1(10835,1408)
  Bottom Layer w8: v1(8753,2676) 8752,2675 8556.9,2675 8339,2892.9 8339,3234.1 8650.9,3546 9215.61,3546 9611.61,3942 9758,3942 v1(9775.61,3924.39) ; v1(10835,1408) 11019,1592 11019,2201.02 11037,2219.02 11037,2533.68 11040,2536.68 11040,2846.26 11081,2887.26 11081,3453.55 11109.67,3482.22 11109.67,3492.67 v1(11128,3511)
IRQ11: J5.26 J6.30 U1.154 | length 6949.5
  Top Layer w8: v1(8614,2697) 8617.25,2697 8621.03,2700.79 J6.30@8681.1,2700.79 ; J5.26@10000,4330.71 10000,4324.8 9951,4275.8 9951,4233.78 9917.57,4200.35 9840.09,4200.35 9745,4105.25 9745,3911.57 9731,3897.57 9731,3685.78 9782.78,3634 10976.11,3634 v1(11072.11,3538) ; v1(10724,1422) 10724.81,1422.81 10776.04,1422.81 U1.154@10776.77,1423.54
  Bottom Layer w8: v1(8614,2697) 8557.53,2697 8355,2899.53 8355,3227.47 8657.53,3530 9222.24,3530 9618.24,3926 9731,3926 v1(9745.42,3911.57) ; v1(10724,1422) 10724,1475 10939,1690 10939,2234.16 10954,2249.16 10954,2874.26 10946,2882.26 10946,3185.65 11033,3272.65 11033,3498.89 v1(11072.11,3538)
IRQ12: C7.1 CON1.1 J5.24 R16.1 R49.1 U1.155 | length 9446.7
  Top Layer w8: R49.1@8144,1957 8144,1958.5 8200.5,2015 8220,2015 8264.85,2059.85 8264.85,2088.85 v1(8312,2136) ; J5.24@9921.26,4330.71 9921.26,4324.8 9885.42,4288.96 9885.42,4232.42 9869.35,4216.35 9833.46,4216.35 9715,4097.88 9715,3679.16 9776.16,3618 10961,3618 v1(11087.67,3491.33) ; U1.155@10776.77,1443.23 10776.91,1443.09 10835.91,1443.09 v1(10836.06,1442.94)
  Bottom Layer w8: CON1.1@7862.2,4251.97 7862.2,4257.87 7832,4288.08 7832,4353 7903,4424 8136,4424 8215,4345 8215,4307 8233,4289 8291.71,4289 8337,4243.71 ; R16.1@8353.61,2135.55 8307.45,2135.55 8157,2286 8157,2760.45 8130,2787.45 8130,3327.88 8262.11,3459.99 8262.11,3835.11 8380,3953 8380,4002.48 8338.5,4043.98 C7.1@8337,4043.98 8337,4243.71 ; J5.24@9921.26,4330.71 9921.26,4336.61 9869.87,4388 8876,4388 8731.71,4243.71 8337,4243.71 ; v1(10836.06,1442.94) 11003,1609.89 11003,2207.65 11021,2225.65 11021,2541.32 11024,2544.32 11024,2852.89 11065,2893.89 11065,3468.66 v1(11087.67,3491.33)
IRQ14: CF1.37 J5.20 U1.158 | length 5802.7
  Top Layer w8: J5.20@9763.78,4330.71 9793.5,4300.99 9793.5,4221.63 9671,4099.14 9671,3677.9 9762.9,3586 10930.77,3586 10948.77,3568 v1(10976,3568) ; U1.158@10653.54,1567.56 10653.54,1643.54 10682,1672 v1(10722,1672) ; v1(10816,2632) 10883,2699 11165,2699 11178,2712 11276.89,2712 11280.89,2716 11444.62,2716 11451.63,2723.01 11451.75,2723.01 11888.39,3159.65 CF1.37@12147.64,3159.65
  Bottom Layer w8: v1(10722,1672) 10724.3,1674.3 10742.28,1674.3 10810,1742.02 10810,2568.51 10816,2574.51 v1(10816,2632) 10817,2633 10817,2927.07 10812,2932.07 10812,3349 10915,3452 10915,3531 10952,3568 v1(10976,3568)
IRQ15: J5.22 J6.32 U1.159 | length 6651.7
  Top Layer w8: J6.32@8681.1,2720.47 8681.87,2719.7 8752.23,2719.7 v1(8753,2718.93) ; J5.22@9842.52,4330.71 9842.52,4324.8 9812.8,4295.09 9812.8,4218.31 9693,4098.51 9693,3678.53 9769.53,3602 10942.64,3602 10951.7,3592.94 v1(10954.94,3592.94) ; U1.159@10633.86,1567.56 10633.86,1646.49 10684.32,1696.94 10733.81,1696.94 v1(10734.43,1697.57)
  Bottom Layer w8: v1(8753,2718.93) 8752.93,2719 8558.16,2719 8371,2906.16 8371,3220.84 8664.16,3514 9228.86,3514 9617.86,3903 9692,3903 v1(9693,3904) ; v1(10734.43,1697.57) 10735.68,1697.57 10794,1755.89 10794,3358 10899,3463 10899,3537.63 10954.32,3592.94 v1(10954.94,3592.94)
IRQEN: U21.11 U21.12 U29.12 U33.9 | length 2013.2
  Top Layer w8: v1(12136,2316) 12136.14,2316.14 12158,2316.14 12169.86,2328 12308.89,2328 12319.89,2317 v1(12470,2317) 12607,2317 12640,2350 13223.31,2350 13224.02,2349.3 13231.7,2349.3 v1(13234,2347)
  Bottom Layer w8: U33.9@12043.78,2292.52 12044.02,2292.76 12112.76,2292.76 v1(12136,2316) ; v1@12470,2314 v1(12470,2317) 12470,2361.2 12502.5,2393.7 U21.11@12531.5,2393.7 U21.12@12531.5,2443.7 ; v1(13234,2347) 13234,2278.32 13231,2275.32 13231,2188 13259,2160 13259,1957.37 13295,1921.37 13295,1857.82 13345.02,1807.8 U29.12@13374.02,1807.8
IRQEN#: U21.13 U33.13 | length 509
  Bottom Layer w8: U33.13@12043.78,2493.7 12046.46,2491.02 12084.44,2491.02 12105,2491 12130.7,2516.7 12399.3,2516.7 12422.3,2493.7 U21.13@12531.5,2493.7
KBCLK: C6.1 CON1.4 R46.1 R81.1 U1.122 | length 6347.8
  Top Layer w8: v1(8312.83,1959.17) 8343.83,1959.17 8344,1959 8455,1959 8622,2126 8981.67,2126 9069.67,2038 9234.46,2038 9465,1807.46 9465,855 v1(9467,853) ; v1(9711.06,848.94) 9723.11,861 10587,861 10654.38,793.62 U1.122@10776.77,793.62
  Bottom Layer w8: CON1.4@7940.94,4330.71 7945.76,4325.9 7945.76,4295.09 7989.97,4250.88 7989.97,4221.59 8101,4110.56 C6.1@8101,4043.98 8102.5,4043.98 8140,4006.48 8140,3880 8180,3840 8180,3491.89 8054.89,3366.77 8054.89,2753.11 8105,2703 8105,2177.72 8167.51,2115.21 8167.51,2069.49 8278.61,1958.39 8313.61,1958.39 8314.4,1959.17 8352.83,1959.17 R81.1@8353.61,1958.39 ; v1(9467,853) 9569.5,853 9572.5,856 9675.75,856 9682.75,849 9711,849 v1(9711.06,848.94)
KBDATA: C5.1 CON1.3 R47.1 R82.1 U1.123 | length 6689.1
  Top Layer w8: R47.1@8277.33,1957 8277.33,1985.33 v1(8310,2018) 8490,2018 8614,2142 8988.3,2142 9076.3,2054 9241.09,2054 9487,1808.09 9487,864.11 9489,862.11 9489,843.89 9485,839.89 v1(9485,813) ; v1(9635,830.68) 9661.68,830.68 9708,877 10593.63,877 10657.32,813.31 U1.123@10776.77,813.31
  Bottom Layer w8: CON1.3@7940.94,4251.97 7940.94,4257.87 7910,4288.82 7910,4352 7934,4376 8035,4376 8054,4357 8054,4186 8163.5,4076.5 8163.5,4058.48 8178,4043.98 C5.1@8179.5,4043.98 8181,4043.98 8195.5,4029.48 8195.5,4023.5 8219,4000 8219,3910 8203,3894 8203,3484.47 8077.89,3359.36 8077.89,2762.64 8121,2719.53 8121,2184.35 8183.51,2121.83 8183.51,2104.49 8270.56,2017.44 R82.1@8353.61,2017.44 ; v1(9485,813) 9485.35,813 9503.03,830.68 v1(9635,830.68)
KBSJ: R9.2 U1.119 U8.22 | length 1178
  Top Layer w8: U1.119@10776.77,734.57 10845.57,734.57 11154,1043 11154,1331.37 11272.63,1450 v1(11345,1450) 11345.73,1450.73 11345.73,1522.89 U8.22@11346.46,1523.62
  Bottom Layer w8: R9.2@11278,1458 11286,1450 v1(11345,1450)
KEY_line1: J9.1 U40.19 | length 694.7
  Top Layer w8: U40.19@7986.72,2501 v1(8081,2501)
  Bottom Layer w8: J9.1@8027.56,1925.2 8027.56,2151.56 8084,2208 8084,2483.11 8083.3,2483.82 8083.3,2498.7 v1(8081,2501)
KEY_line2: J9.2 U40.20 | length 657.9
  Top Layer w8: U40.20@7986.57,2481.47 8051.28,2481.47 8058.75,2474 v1(8062,2474)
  Bottom Layer w8: J9.2@7988.19,1925.2 7988.19,2146.19 8062,2220 v1(8062,2474)
KEY_line3: J9.3 U40.21 | length 622.1
  Top Layer w8: U40.21@7986.57,2461.79 8029.77,2461.79 8039.56,2452 v1(8040,2452)
  Bottom Layer w8: J9.3@7948.82,1925.2 7948.82,2129.45 8040,2220.63 v1(8040,2452)
KEY_line4: J9.4 U40.22 | length 591.5
  Top Layer w8: v1(7934,2442) 7934.05,2442.05 7979.32,2442.05 U40.22@7980,2441.37
  Bottom Layer w8: J9.4@7909.45,1925.2 7910.22,1925.97 7910.22,2118.22 7956,2164 7956,2420 v1(7934,2442)
KEY_line5: J9.5 U40.23 | length 578.1
  Top Layer w8: v1(7931,2406) 7931,2408.25 7935.3,2412.54 7935.3,2413.3 7944.42,2422.42 U40.23@7986.57,2422.42
  Bottom Layer w8: J9.5@7870.08,1925.2 7869.54,1925.74 7869.54,2115.54 7940,2186 7940,2394.75 7931,2403.75 v1(7931,2406)
KEY_line6: J9.6 U40.26 | length 577.2
  Top Layer w8: v1(7830,2162) 7853.89,2162 7863.89,2152 7902.96,2152 8058.42,2307.46 U40.26@8058.42,2350.57
  Bottom Layer w8: v1(7830,2162) 7830.71,2161.29 J9.6@7830.71,1925.2
KEY_line7: J9.7 U40.27 | length 626.6
  Top Layer w8: v1(7791,2145) 7815.89,2145 7824.89,2136 7909.59,2136 8078.1,2304.51 U40.27@8078.1,2350.57
  Bottom Layer w8: v1(7791,2145) 7791.17,2144.83 7791.17,1925.37 J9.7@7791.34,1925.2
KEY_line8: J9.8 U40.28 | length 671.1
  Top Layer w8: v1(7763,2129) 7765.3,2126.7 7778.18,2126.7 7784.89,2120 7916.22,2120 8097.79,2301.57 U40.28@8097.79,2350.57
  Bottom Layer w8: J9.8@7751.97,1925.2 7751.97,2044.97 7763,2056 v1(7763,2129)
KEY_line9: J9.9 U40.18 | length 793.1
  Top Layer w8: v1(7729.63,2183.37) 7768.26,2222 7832,2222 7858.63,2222 7909,2272.37 7909,2487.26 7942.09,2520.34 7986.07,2520.34 U40.18@7986.57,2520.84
  Bottom Layer w8: J9.9@7712.6,1925.2 7712.6,2051.6 7736,2075 7736,2124.38 7729.63,2130.75 v1(7729.63,2183.37)
KEY_line10: J9.10 U40.29 | length 745
  Top Layer w8: v1(7713,2113) 7747.89,2113 7756.89,2104 7922.84,2104 8117.47,2298.63 U40.29@8117.47,2350.57
  Bottom Layer w8: J9.10@7673.23,1925.2 7673.23,2051.23 7713,2091 v1(7713,2113)
KEY_line11: J9.11 U40.30 | length 804.5
  Top Layer w8: v1(7684,2107) 7703,2088 7929.47,2088 8137.16,2295.69 U40.30@8137.16,2350.57
  Bottom Layer w8: J9.11@7633.86,1925.2 7633.86,2056.86 v1(7684,2107)
KEY_line12: J9.12 U40.31 | length 872.4
  Top Layer w8: v1(7643,2102) 7673,2072 7936.1,2072 8156.84,2292.74 U40.31@8156.84,2350.57
  Bottom Layer w8: J9.12@7594.49,1925.2 7594.49,2053.49 v1(7643,2102)
KEY_line13: J9.13 U40.32 | length 950.6
  Top Layer w8: v1(7611.5,2106.5) 7611.5,2103.25 7621,2093.75 7621,2092.89 7657.89,2056 7942.73,2056 8176.53,2289.8 U40.32@8176.53,2350.57
  Bottom Layer w8: J9.13@7555.12,1925.2 7555.12,2050.12 v1(7611.5,2106.5)
KEY_line14: J9.14 U40.41 | length 1352.2
  Top Layer w8: v1(7515,1980) 7583,1912 8002.37,1912 8383.91,2293.54 8383.91,2443.09 8346.26,2480.74 8308.16,2480.74 U40.41@8307.43,2481.47
  Bottom Layer w8: v1(7515,1980) 7515.37,1979.63 7515.37,1925.57 J9.14@7515.75,1925.2
KEY_line15: J9.15 U40.24 | length 876.7
  Top Layer w8: v1(7476.38,2137.8) 7715.26,2137.8 7783.46,2206 7865.25,2206 7986.57,2327.31 U40.24@7986.57,2402.73
  Bottom Layer w8: J9.15@7476.38,1925.2 v1(7476.38,2137.8)
KEY_line16: J9.17 U40.42 | length 1511.5
  Top Layer w8: v1(7433.07,1980) 7517.07,1896 8009,1896 8399.91,2286.91 8399.91,2449.72 8348.47,2501.16 U40.42@8307.43,2501.16
  Bottom Layer w8: J9.17@7397.64,1925.2 7397.64,1947.68 7429.96,1980 v1(7433.07,1980)
KEY_line17: J9.24 U40.7 | length 1649.8
  Top Layer w8: v1(7122.05,1988.19) 7124.34,1990.48 7124.34,2000.33 7161.42,2037.4 7206.69,2037.4 7224.41,2055.12 7255.91,2055.12 7287.4,2086.61 7295.28,2086.61 7346.46,2137.8 7440.94,2137.8 7464.57,2161.42 7670.42,2161.42 7747,2238 7852,2238 7893,2279 7893,2649 7971,2727 8116,2727 8136.43,2706.57 8136.43,2672.16 U40.7@8137.16,2671.43
  Bottom Layer w8: J9.24@7122.05,1925.2 v1(7122.05,1988.19)
KEY_ROW1: J9.18 U40.33 | length 1242.1
  Top Layer w8: v1(7338.58,2098.43) 7354.16,2114 7572.88,2114 7646.88,2040 7949.35,2040 8196.21,2286.86 U40.33@8196.21,2350.57
  Bottom Layer w8: v1(7338.58,2098.43) 7358.27,2078.74 J9.18@7358.27,1925.2
KEY_ROW2: J9.19 U40.34 | length 1258.9
  Top Layer w8: v1(7318.9,2070.87) 7346.46,2070.87 7373.59,2098 7566.25,2098 7640.25,2024 7955.98,2024 8215.9,2283.92 U40.34@8215.9,2350.57
  Bottom Layer w8: J9.19@7318.9,1925.2 v1(7318.9,2070.87)
KEY_ROW3: J9.20 U40.35 | length 1305.8
  Top Layer w8: v1(7279.53,2047.24) 7346.46,2047.24 7381.21,2082 7559.63,2082 7633.63,2008 7962.61,2008 8235.58,2280.97 U40.35@8235.58,2350.57
  Bottom Layer w8: J9.20@7279.53,1925.2 v1(7279.53,2047.24)
KEY_ROW4: J9.21 U40.36 | length 1357
  Top Layer w8: v1(7240.16,2027.56) 7242.45,2025.26 7250.82,2025.26 ; 7250.84,2025.24 7347.08,2025.24 7387.84,2066 7553,2066 7627,1992 7969.24,1992 8255.27,2278.03 U40.36@8255.27,2350.57
  Bottom Layer w8: J9.21@7240.16,1925.2 v1(7240.16,2027.56)
KEY_ROW5: J9.22 U40.37 | length 1473.9
  Top Layer w8: v1(7200.79,1980.31) 7350.39,1980.31 7404.08,2034 7539.25,2034 7613.25,1960 7982.49,1960 8294,2271.51 8294,2400.97 8295.76,2402.73 U40.37@8307.43,2402.73
  Bottom Layer w8: J9.22@7200.79,1925.2 v1(7200.79,1980.31)
KEY_ROW6: J9.23 U40.38 | length 1558
  Top Layer w8: v1(7161.42,2003.94) 7349.4,2003.94 7395.46,2050 7545.88,2050 7619.88,1976 7975.86,1976 8278,2278.14 8278,2379.73 8262.95,2394.78 8262.95,2410.15 8274.49,2421.69 8306.7,2421.69 U40.38@8307.43,2422.42
  Bottom Layer w8: J9.23@7161.42,1925.2 v1(7161.42,2003.94)
KEY_ROW7: J9.25 U40.39 | length 1718.6
  Top Layer w8: v1(7082.68,1984.25) 7110.24,1956.69 7349.4,1956.69 7410.71,2018 7532.63,2018 7606.63,1944 7989.12,1944 8351.91,2306.8 8351.91,2429.83 8340.37,2441.37 8308.16,2441.37 U40.39@8307.43,2442.1
  Bottom Layer w8: J9.25@7082.68,1925.2 v1(7082.68,1984.25)
KEY_ROW8: J9.26 U40.40 | length 1822.2
  Top Layer w8: v1(7043.31,1984.25) 7090.55,1937.01 7352.34,1937.01 7417.33,2002 7526,2002 7600,1928 7995.75,1928 8367.91,2300.17 8367.91,2436.46 8343.32,2461.06 8308.16,2461.06 U40.40@8307.43,2461.79
  Bottom Layer w8: J9.26@7043.31,1925.2 v1(7043.31,1984.25)
L: C57.1 C58.2 P1.3 VR1.2 | length 1417.2
  Top Layer w15: P1.3@6137.8,3062.99 6341.17,3062.99 6356.91,3047.24 v1(6358.27,3047.24) 6436.99,2968.52 C58.2@6755.91,2968.52 C57.1@6837,2968.5
  Bottom Layer w15: v1(6358.27,3047.24) 6358.27,2877.27 6313,2832 6313,2676 6385.83,2603.17 VR1.2@6385.83,2417.32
